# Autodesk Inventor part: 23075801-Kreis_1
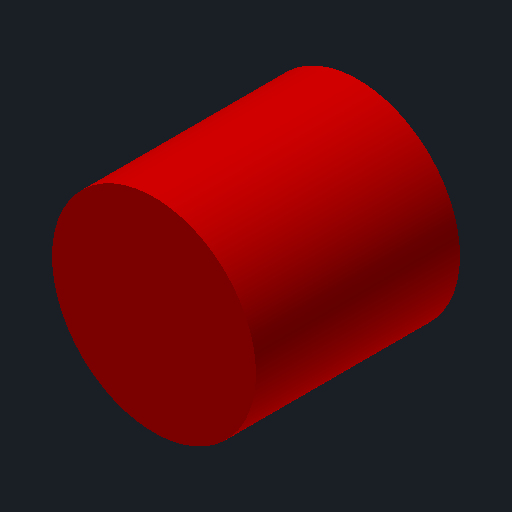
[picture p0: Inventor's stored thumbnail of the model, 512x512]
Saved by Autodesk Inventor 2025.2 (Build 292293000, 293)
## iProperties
Company: Ed. Züblin AG
Created: 2025-03
Part Number: 23075801-Kreis_1
Material: Stahlbeton C30/37
Document SubType Name: Modeling
Designer: FrodlSte
Mass: 1.9635e+06 g
Surface Area: 47123.9 cm^2
Volume: 785398 cm^3
Density: 2.5 g/cm^3
Appearance: Beton C30/37
Description: Abdichtungstraeger
z_Bereich: Tunnelbau
z_Direktion: Tief- und Tunnelbau
z_Konzerneinheit: Zentrale Technik
z_Matchkey: =<z_Matchkey_010>_<z_Matchkey_020>_<z_Matchkey_030>_<z_Matchkey_040>_<z_Matchkey_050>_<z_Matchkey_060>_<z_Matchkey_070>_<z_Matchkey_080>_<z_Matchkey_090>_<z_Mat
cpiComponentType: Attribut
cpiFitMatchkey: =<z_Matchkey>
z_Matchkey_010: xxxxx
z_Matchkey_020: 5DTUB
z_Matchkey_030: xxx
z_Matchkey_040: xxx
z_Matchkey_050: xxx
z_Matchkey_060: xxx
z_Matchkey_070: xxx
z_Matchkey_080: xxx
z_Matchkey_090: xxx
z_Matchkey_100: xxx
z_Matchkey_110: xxx
z_Matchkey_120: xxxxxxx
z_Matchkey_130: KALO
z_Matchkey_140: LAIB
DocNumber: 23075801-Kreis_1.ipt
Folder: DL23075801-DE-Pfaffensteigtunnel\BIM\Testmodell
VDS_Category: 09 - BIM - Konstruktion
DBSet_Beton:Betondeckung_mm: -9999,900000000001
DBSet_Beton:Betonstahlguete: BST_500A
DBSet_Beton:Bewehrungsgehalt: -99999.0
DBSet_Beton:Druckfestigkeitsklasse: C12/15
DBSet_Beton:Expositionsklasse_X: ND
DBSet_Beton:Expositionsklasse_XA: ND
DBSet_Beton:Expositionsklasse_XC: ND
DBSet_Beton:Expositionsklasse_XD: ND
DBSet_Beton:Expositionsklasse_XF: ND
DBSet_Beton:Expositionsklasse_XM: ND
DBSet_Beton:Expositionsklasse_XS: ND
DBSet_Beton:Feuchtigkeitsklasse: ND
DBSet_Beton:Groesstkorn: 11
DBSet_Beton:Herstellungsort: FTB
DBSet_Beton:Luftporenbeton: ND
DBSet_Beton:PP_Faser: False
DBSet_Beton:PP_Faser_Gehalt: -99999.0
DBSet_Beton:Rohdichte: -99999.0
DBSet_Beton:Sichtbetonklasse: ND
DBSet_Beton:Unbewehrter_Beton: False
DBSet_Beton:Wasserzementwert_max: -99999.0
DBSet_Beton:WU_Beton: ND
DBSet_Beton:Zusatzmittel: ND
DBSet_Element:010_Eigentuemer: DBE
DBSet_Element:020_Autor: ND
DBSet_Element:030_Projektnummer: G.016268527
DBSet_Element:040_Bereich: ND
DBSet_Element:050_Vertragspartner: ND
DBSet_Element:060_Gewerk: ND
DBSet_Element:070_Bauwerk: EW
DBSet_Element:080_Bauwerksnummer: 17030
DBSet_Element:090_Bezeichnung: ND
DBSet_Element:100_Gruppe: Abdichtung
DBSet_Element:110_Element: Abdichtungstraeger
DBSet_Element:120_Elementtyp: ND
DBSet_Element:130_Identifikationsnummer: ND
DBSet_Element:140_Position_1: KALO
DBSet_Element:150_Position_2: FIRS
DBSet_Element:160_PUID: ND
DBSet_Element:170_Hauptmaterialitaet: Baugrund
DBSet_Element:171_Materialindikator_1: ND
DBSet_Element:172_Materialindikator_2: ND
DBSet_Geometrie:Dicke: -99999.0
DBSet_Geometrie:Flaeche: -99999.0
DBSet_Geometrie:Volumen_Solid: 7.21
DBSet_Position:Streckenachse: ND
DBSet_Position:Streckenkilometer_Anfang: -99999
DBSet_Position:Streckenkilometer_Ende: -99999
DBSet_Position:Tunnelachse: ND
DBSet_Position:Tunnelmeter_Anfang: -99999
DBSet_Position:Tunnelmeter_Ende: -99999
DBSet_TP:Status: ABB
z_DBSet_Beton:Betondeckung_mm: -99999,000 mm
z_DBSet_Beton:Betonstahlguete: Nicht definiert
z_DBSet_Beton:Bewehrungsgehalt: -99999,000 oE
z_DBSet_Beton:Druckfestigkeitsklasse: Beton C25/30
z_DBSet_Beton:Expositionsklasse_X: Nicht definiert
z_DBSet_Beton:Expositionsklasse_XA: Nicht definiert
z_DBSet_Beton:Expositionsklasse_XC: Nicht definiert
z_DBSet_Beton:Expositionsklasse_XD: Nicht definiert
z_DBSet_Beton:Expositionsklasse_XF: Nicht definiert
z_DBSet_Beton:Expositionsklasse_XM: Nicht definiert
z_DBSet_Beton:Expositionsklasse_XS: Nicht definiert
z_DBSet_Beton:Feuchtigkeitsklasse: Nicht definiert
z_DBSet_Beton:Groesstkorn: 8 mm
z_DBSet_Beton:Herstellungsort: Spritzbeton
z_DBSet_Beton:Luftporenbeton: nicht definiert
z_DBSet_Beton:PP_Faser: Falsch
z_DBSet_Beton:PP_Faser_Gehalt: -99999,000 oE
z_DBSet_Beton:Rohdichte: -99999,000 oE
z_DBSet_Beton:Sichtbetonklasse: Nicht definiert
z_DBSet_Beton:Unbewehrter_Beton: Wahr
z_DBSet_Beton:Wasserzementwert_max: -99999,000 oE
z_DBSet_Beton:WU_Beton: False
z_DBSet_Beton:Zusatzmittel: nicht definiert
z_DBSet_Element:010_Eigentuemer: DBInfraGo
z_DBSet_Element:020_Autor: Vertragspartner 2 ZB
z_DBSet_Element:030_Projektnummer: Gaeubahn Nord HP Goldberg (DBnfraGO, BK11)
z_DBSet_Element:040_Bereich: PFA 1 Tunnel
z_DBSet_Element:050_Vertragspartner: Tunnel
z_DBSet_Element:060_Gewerk: Tunnelbau
z_DBSet_Element:070_Bauwerk: SBW-Tu
z_DBSet_Element:080_Bauwerksnummer: zzz (leer)
z_DBSet_Element:090_Bezeichnung: zzz (leer)
z_DBSet_Element:100_Gruppe: Abdichtung
z_DBSet_Element:110_Element: Abdichtungstraeger
z_DBSet_Element:120_Elementtyp: Abdichtungstraeger
z_DBSet_Element:130_Identifikationsnummer: Nicht definiert
z_DBSet_Element:140_Position_1: Kalotte
z_DBSet_Element:150_Position_2: Nicht definiert
z_DBSet_Element:160_PUID: Nicht definiert
z_DBSet_Element:170_Hauptmaterialitaet: Beton
z_DBSet_Element:171_Materialindikator_1: Spritzbeton
z_DBSet_Element:172_Materialindikator_2: Nicht definiert
z_DBSet_Geometrie:Dicke: 0,020 m
z_DBSet_Geometrie:Flaeche: -99999,000 m^2
z_DBSet_Position:Streckenachse: zzz (leer)
z_DBSet_Position:Streckenkilometer_Anfang: -11111,000 oE
z_DBSet_Position:Streckenkilometer_Ende: -11111,000 oE
z_DBSet_Position:Tunnelachse: zzz (leer)
z_DBSet_Position:Tunnelmeter_Anfang: -11111,000 oE
z_DBSet_Position:Tunnelmeter_Ende: -11111,000 oE
z_DBSet_TP:Status: Neubau
z_DBSet_Geometrie:Volumen_Solid: -11111,000 m^3
Author: FrodlSte
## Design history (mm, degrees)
derived "23075801-Skelett.ipt"
node "Kreis_1"
node "Volumenkörpern"
node "Oberflächenkörpern"
feature "Kreis_1::23075801-Skelett.ipt" dims "d4" = 10
tag "Bezeichnung1"
